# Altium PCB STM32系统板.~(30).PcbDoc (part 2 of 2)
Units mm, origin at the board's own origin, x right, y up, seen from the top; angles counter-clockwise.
Board outline 191.7 x 146.7 mm, 4 copper layers (TopLayer, MidLayer1, MidLayer2, BottomLayer); 154 components, 101 nets, 554 pads, 177 vias.
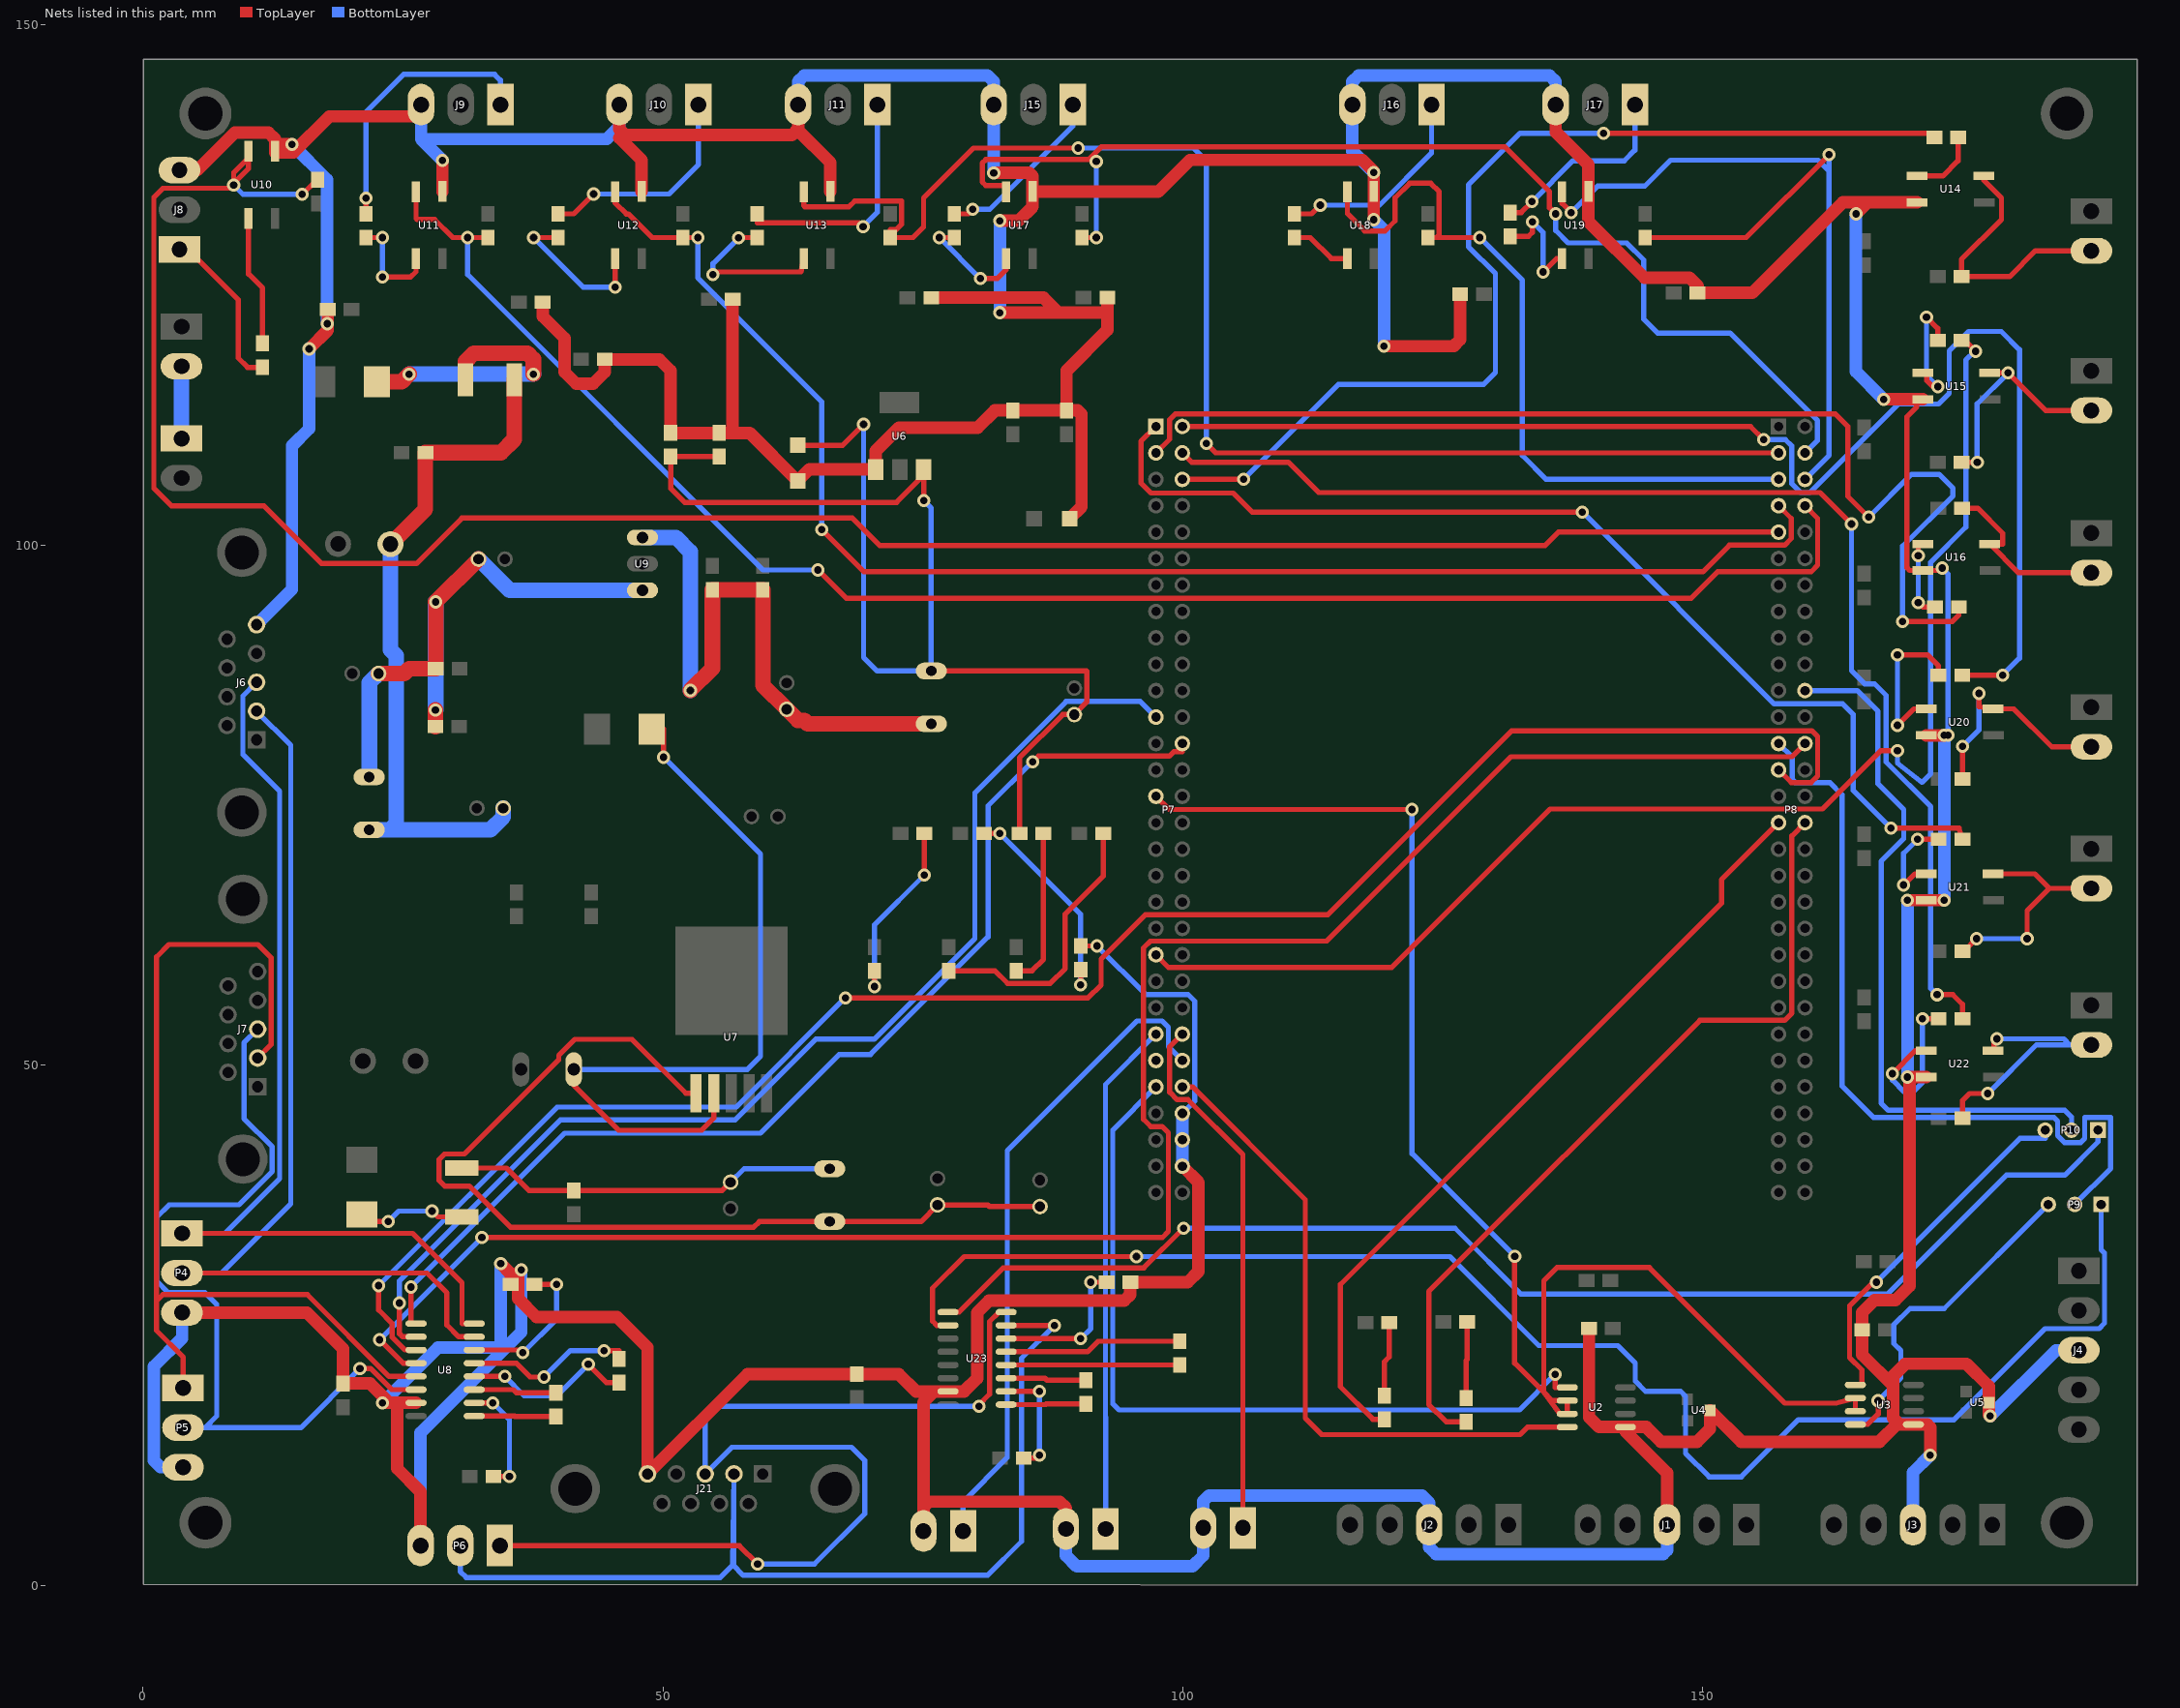
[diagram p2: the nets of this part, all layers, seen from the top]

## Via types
v1: diameter 1.27, hole 0.711, TopLayer to BottomLayer, 177 vias

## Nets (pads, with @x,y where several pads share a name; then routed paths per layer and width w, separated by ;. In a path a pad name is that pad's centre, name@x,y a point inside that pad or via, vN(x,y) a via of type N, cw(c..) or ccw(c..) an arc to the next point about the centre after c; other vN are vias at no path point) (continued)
GND-SYS: C19.1 C20.1 C23.2 C24.2 C25.2 C26.2 C29.2 C30.2 C31.2 C46.2 C48.1 C50.2 C51.1 C54.2 C55.1 C56.1 C57.1 C58.1 C59.1 J1.3 J2.3 J3.3 J4.3 J6.5 J8.3 J9.3 J10.3 J11.3 J15.3 J16.3 J17.3 J21.5 LED6.2 P4.3 P5.3 P6.3 P7.54 P7.56 P7.58 R11.2 S2.2 S3.2 S4.2 U2.5 U3.5 U4.3 U5.3 U6.1 U8.15 U10.3 U11.3 U12.3 U13.3 U14.2 U15.2 U16.2 U17.3 U18.3 U19.3 U20.2 U21.2 U22.2 U23.15 | length 1068.5
  TopLayer w0.5: LED6.2@90.176,61.457 v1(91.725,61.457) ; U15.2@171.15,114.01 170.56,114.01 170.56,113.279 169.62,112.339 169.62,97.821 169.881,97.56 U16.2@171.15,97.56 172.773,97.56 v1(172.998,97.785) ; U20.2@171.474,81.71 v1(173.202,81.71) v1(173.583,81.71)
  TopLayer w1.2: J8.3@3.5,136.05 5.217,136.05 8.837,139.67 12.064,139.67 12.69,139.044 U10.3@12.69,138.527 ; P4.3@3.75,26.2 15.76,26.2 19.232,22.728 C46.2@19.232,19.388 21.834,19.388 23.697,17.525 ; v1(14.325,138.527) U10.3@12.69,138.527 ; v1(15.976,118.867) 17.764,120.656 v1@17.764,121.341 ; v1(17.703,121.28) v1@17.764,121.341 ; C56.1@17.764,122.65 v1@17.764,121.341 ; v1(23.037,17.525) 23.697,17.525 ; U8.15@26.256,17.525 24.434,17.525 ; P6.3@26.69,3.8 26.69,8.961 24.434,11.218 24.434,17.525 ; J9.3@26.74,142.35 26.74,141.219 17.922,141.219 14.469,137.766 12.69,137.766 U10.3@12.69,137.872 U10.3@12.69,138.527 ; U11.3@28.79,134 v1(28.79,136.98) ; v1(34.391,30.907) 35.35,29.948 C31.2@35.35,28.9 ; v1(36.372,30.323) 36.074,30.025 36.074,27.555 37.847,25.782 45.586,25.782 48.515,22.853 J21.5@48.515,10.69 58.113,20.288 C50.2@68.632,20.288 72.668,20.288 74.331,18.625 76.072,18.625 ; C57.1@38.436,123.35 38.436,121.991 40.537,119.89 40.537,116.632 41.655,115.514 43.282,115.514 44.4,116.632 R11.2@44.4,117.85 49.656,117.85 50.732,116.774 C23.2@50.732,110.788 C24.2@55.4,110.788 56.442,110.788 ; J10.3@45.79,142.35 45.79,140 46.209,139.581 ; U12.3@47.95,134 47.95,137.003 45.79,139.163 46.209,139.581 ; C58.1@56.698,123.632 56.698,111.044 56.442,110.788 ; J11.3@62.99,142.35 62.99,140 ; U13.3@66.09,134 66.09,136.774 62.99,139.874 62.99,140 ; U6.1@70.467,107.26 U6.1@70.467,107.285 ; S2.2@75.05,5.2 75.05,7.508 ; C59.1@75.798,123.782 86.6,123.782 88.035,122.347 ; v1(81.8,135.784) 85.216,135.784 85.54,135.46 U17.3@85.54,134 U17.3@85.54,133.98 ; v1(82.397,122.347) 88.035,122.347 ; v1(82.397,131.186) 84.2,131.186 85.54,132.526 U17.3@85.54,133.98 ; S3.2@88.75,5.4 88.75,7.412 88.14,8.022 75.564,8.022 75.05,7.508 ; C30.2@89.114,102.55 90.245,103.681 90.245,112.568 89.875,112.938 C26.2@88.8,112.938 ; C48.1@92.736,123.8 92.736,122.728 ; P7.58@99.94,40.28 101.497,38.723 101.497,30.159 100.456,29.118 C54.2@94.938,29.118 94.938,27.929 94.36,27.351 81.355,27.351 80.212,26.208 80.212,19.883 78.954,18.625 U23.15@77.406,18.625 76.072,18.625 ; v1(118.35,131.288) U18.3@118.35,134 v1(118.35,135.809) 118.35,135.936 117.258,137.028 100.685,137.028 97.637,133.98 U17.3@85.54,133.98 ; v1(119.328,119.121) 126.034,119.121 126.652,119.739 C51.1@126.652,124.118 ; J17.3@135.84,142.35 135.84,139.721 138.99,136.571 U19.3@138.99,134 138.99,131.085 144.375,125.7 148.716,125.7 149.486,124.93 C55.1@149.486,124.25 154.759,124.25 163.459,132.95 165.821,132.95 ; C19.1@139.052,24.668 139.052,16.147 140.004,15.195 U2.5@142.544,15.195 ; J1.3@146.55,5.8 146.55,10.79 142.544,14.796 U2.5@142.544,15.195 ; v1(164.718,131.847) 165.821,132.95 ; v1(167.391,114.01) U15.2@171.15,114.01 ; v1(169.671,65.85) U21.2@171.474,65.85 v1(173.202,65.85) ; U14.2@170.6,132.95 165.821,132.95 ; U22.2@171.474,48.85 v1(169.671,48.85) 169.874,48.647 169.874,28.748 168.528,27.402 166.496,27.402 165.314,26.22 C20.1@165.314,24.55 165.314,22.144 168.299,19.159 ; U20.2@171.474,81.71 v1(173.202,81.71) ; v1(171.855,12.496) 171.855,15.166 171.576,15.445 U3.5@170.244,15.445 168.902,15.445 168.766,15.581 ; v1(177.621,16.251) 177.5,16.372 U5.3@177.5,17.55 177.5,19.116 175.335,21.28 169.468,21.28 168.299,20.112 168.299,19.159 ; 23.697,17.525 24.434,17.525 ; 46.209,139.581 46.374,139.416 62.406,139.416 62.99,140 ; 56.442,110.788 58.333,110.788 C29.2@62.95,106.171 64.064,107.285 U6.1@70.467,107.285 ; U6.1@70.467,107.285 70.467,109.063 72.702,111.298 80.274,111.298 81.914,112.938 C25.2@83.65,112.938 C26.2@88.8,112.938 ; 75.05,7.508 75.05,17.603 76.072,18.625 ; 88.035,122.347 92.355,122.347 92.736,122.728 ; C26.2@88.8,112.938 88.8,116.759 92.736,120.695 92.736,122.728 ; U2.5@142.544,15.195 144.55,15.195 145.958,13.787 149.435,13.787 150.68,15.032 U4.3@150.68,16.8 153.693,13.787 166.972,13.787 168.766,15.581 ; 168.299,19.159 168.299,16.048 168.766,15.581
  BottomLayer w0.5: v1(91.725,61.457) 96.392,56.79 100.481,56.79 101.14,56.131 101.14,46.56 P7.54@99.94,45.36 ; v1(172.998,97.785) 173.583,97.201 v1(173.583,81.71)
  BottomLayer w1.2: P4.3@3.75,26.2 3.758,26.2 3.758,23.744 1.04,21.026 1.04,11.984 1.694,11.33 P5.3@3.85,11.33 ; J6.5@10.92,92.345 14.325,95.75 14.325,109.545 15.976,111.196 v1(15.976,118.867) ; v1(14.325,138.527) 17.703,135.149 v1(17.703,121.28) ; v1(23.037,17.525) 28.342,22.83 34.391,22.83 v1(34.391,30.907) ; P6.3@26.69,3.8 26.69,14.647 36.372,24.328 v1(36.372,30.323) ; J9.3@26.74,142.35 26.74,139.035 ; v1(28.79,136.98) 26.74,139.03 26.74,139.035 ; J10.3@45.79,142.35 45.79,140.249 44.576,139.035 26.74,139.035 ; J11.3@62.99,142.35 62.99,144.572 63.574,145.156 81.216,145.156 81.8,144.572 J15.3@81.8,142.35 v1(81.8,135.784) ; v1(82.397,122.347) v1(82.397,131.186) ; S3.2@88.75,5.4 88.75,2.84 89.791,1.799 100.909,1.799 101.95,2.84 S4.2@101.95,5.5 101.95,8.068 102.488,8.606 122.994,8.606 123.68,7.92 J2.3@123.68,5.8 123.68,3.644 124.332,2.992 146.194,2.992 146.55,3.348 J1.3@146.55,5.8 ; P7.58@99.94,40.28 P7.56@99.94,42.82 P7.54@99.94,45.36 ; v1(118.35,131.288) 119.328,130.31 v1(119.328,119.121) ; v1(118.35,135.809) 116.29,137.869 J16.3@116.29,142.35 116.29,144.572 116.874,145.156 135.256,145.156 135.84,144.572 J17.3@135.84,142.35 ; v1(164.718,131.847) 164.718,116.683 v1(167.391,114.01) ; v1(169.671,48.85) v1(169.671,65.85) ; J3.3@170.2,5.8 170.2,10.841 v1(171.855,12.496) ; v1(173.202,65.85) v1(173.202,81.71) ; v1(177.621,16.251) 183.96,22.59 J4.3@186.15,22.59
IN1: J8.1 R16.2 | length 16
  TopLayer w0.5: J8.1@3.5,128.43 4.317,128.43 9.143,123.604 9.143,118.004 10.057,117.089 11.5,117.089 R16.2@11.5,117.1
IN1_1: P8.9 R22.1 U10.4 | length 214.9
  TopLayer w0.5: v1(8.711,134.615) v1@8.711,134.768 ; U10.4@10.15,137.846 U10.4@10.15,137.257 ; v1(15.315,133.726) 16.611,135.022 16.8,135.022 R22.1@16.8,135.136 ; P8.9@157.276,101.24 136.092,101.24 134.802,99.95 70.857,99.95 68.216,102.591 30.662,102.591 26.288,98.217 17.169,98.217 11.607,103.78 2.717,103.78 1.04,105.456 1.04,133.447 1.904,134.31 8.254,134.31 v1@8.711,134.768 ; v1@8.711,134.768 8.711,135.818 U10.4@10.15,137.257 ; v1@8.711,134.768 10.15,136.206 U10.4@10.15,137.257
  BottomLayer w0.5: v1(8.711,134.615) 9.6,133.726 v1(15.315,133.726)
IN2: J9.1 R17.2 | length 26.8
  TopLayer w0.5: R17.2@21.45,131.85 v1(21.45,133.359)
  BottomLayer w0.5: v1(21.45,133.359) 21.45,141.664 25.043,145.258 33.801,145.258 34.36,144.699 J9.1@34.36,142.35
IN2_2: P8.8 R23.1 U11.4 | length 164
  TopLayer w0.5: U11.4@26.25,133.975 26.25,131.41 26.365,131.295 28.048,131.295 29.779,129.564 v1(31.216,129.564) R23.1@33.15,129.564 ; v1(64.896,97.607) 67.614,94.89 148.868,94.89 151.408,97.43 160.4,97.43 161.035,98.065 161.035,102.561 P8.8@159.816,103.78
  BottomLayer w0.5: v1(31.216,129.564) 31.216,126.005 59.613,97.607 v1(64.896,97.607)
IN3: J10.1 R18.2 | length 21.2
  TopLayer w0.5: R18.2@39.907,131.85 41.426,131.85 v1(43.328,133.752)
  BottomLayer w0.5: v1(43.328,133.752) 50.57,133.752 53.41,136.591 J10.1@53.41,142.35
IN3_3: P8.7 R24.1 U12.4 | length 143.3
  TopLayer w0.5: U12.4@45.41,133.975 45.41,132.888 46.473,131.825 46.678,131.825 48.939,129.564 R24.1@51.9,129.564 v1(53.339,129.564) ; v1(65.252,101.494) 69.316,97.43 149.986,97.43 152.551,99.995 157.86,99.995 158.495,100.63 158.495,102.561 P8.7@157.276,103.78
  BottomLayer w0.5: v1(53.339,129.564) 53.339,125.7 65.252,113.787 v1(65.252,101.494)
IN4: J17.1 R32.2 | length 18.9
  TopLayer w0.5: R32.2@131.45,131.968 132.519,131.968 v1(133.567,133.016)
  BottomLayer w0.5: v1(133.567,133.016) 137.503,136.952 142.444,136.952 143.46,137.968 J17.1@143.46,142.35
IN4_4: P8.6 R38.1 U19.4 | length 82.8
  TopLayer w0.5: U19.4@136.45,133.975 136.45,132.86 v1(137.337,131.974) ; R38.1@144.45,129.564 154.155,129.564 v1(162.127,137.536)
  BottomLayer w0.5: v1(137.337,131.974) 139.877,134.514 144.398,134.514 146.887,137.003 161.06,137.003 162.127,135.936 ; P8.6@159.816,106.32 162.127,108.631 162.127,135.936 ; v1(162.127,137.536) 162.127,135.936
IN5: J16.1 R31.2 | length 20.3
  TopLayer w0.5: R31.2@110.707,131.85 112.372,131.85 v1(113.207,132.685)
  BottomLayer w0.5: v1(113.207,132.685) 118.906,132.685 123.91,137.689 J16.1@123.91,142.35
IN5_5: P8.5 R37.1 U18.4 | length 72.9
  TopLayer w0.5: U18.4@115.81,133.975 115.81,131.872 117.479,130.203 119.43,130.203 120.395,131.168 120.395,133.396 121.792,134.793 123.824,134.793 124.637,133.98 124.637,129.84 124.361,129.564 ; R37.1@123.55,129.564 124.361,129.564 ; v1(128.548,129.564) 124.361,129.564
  BottomLayer w0.5: v1(128.548,129.564) 132.638,125.475 132.638,108.606 134.923,106.32 P8.5@157.276,106.32
IN6: J15.1 R30.2 | length 17
  TopLayer w0.5: R30.2@78.007,131.85 79.352,131.85 v1(79.78,132.278)
  BottomLayer w0.5: v1(79.78,132.278) 81.406,132.278 89.42,140.292 J15.1@89.42,142.35
IN6_6: P8.4 R36.1 U17.4 | length 114.9
  TopLayer w0.5: U17.4@83,133.975 83,134.564 81.05,134.564 80.695,134.92 80.695,136.723 81.044,137.072 90.932,137.072 ; R36.1@90.3,129.564 v1(91.668,129.564) ; v1(91.668,136.876) 90.932,137.072 ; v1(135.838,131.847) 135.251,132.434 135.251,133.983 130.961,138.273 92.132,138.273 90.932,137.072
  BottomLayer w0.5: v1(91.668,129.564) v1(91.668,136.876) ; v1(135.838,131.847) 135.838,130.246 137.032,129.053 142.671,129.053 144.322,127.402 144.322,121.712 145.643,120.391 152.602,120.391 161.016,111.977 161.016,110.06 P8.4@159.816,108.86
IN7: J11.1 R19.2 | length 23.5
  TopLayer w0.5: R19.2@59.057,131.85 59.057,131.001 68.866,131.001 v1(69.239,130.627)
  BottomLayer w0.5: v1(69.239,130.627) 70.61,131.998 J11.1@70.61,142.35
IN7_7: P8.3 R25.1 U13.4 | length 134
  TopLayer w0.5: U13.4@63.55,133.975 63.55,132.637 63.652,132.535 67.896,132.535 68.427,133.066 72.948,133.066 72.948,130.856 72.44,130.348 71.85,130.348 R25.1@71.85,129.564 74.04,129.564 75.056,130.58 75.056,133.371 79.857,138.171 v1(89.915,138.171) ; v1(102.234,109.774) 103.148,108.86 156.209,108.86 P8.3@157.276,108.86
  BottomLayer w0.5: v1(89.915,138.171) 101.015,138.171 102.234,136.952 v1(102.234,109.774)
KEY1: P7.48 S4.1 | length 51.5
  TopLayer w0.5: P7.48@99.94,52.98 98.729,51.769 98.729,47.392 99.44,46.68 100.481,46.68 105.76,41.402 S4.1@105.76,5.5
KEY2: P7.47 S3.1 | length 49.6
  BottomLayer w0.5: S3.1@92.56,5.4 92.56,16.132 92.55,16.143 92.55,48.13 P7.47@97.4,52.98
KEY3: P7.50 S2.1 | length 63
  BottomLayer w0.5: S2.1@78.86,5.2 78.86,8.022 83.108,12.269 83.108,41.778 95.579,54.25 97.992,54.25 98.602,53.64 98.602,51.778 P7.50@99.94,50.44
KEY4: P7.49
L1: P7.2 R33.2 | length 130.6
  TopLayer w0.5: P7.2@99.94,111.4 154.583,111.4 v1(155.853,110.13) ; R33.2@174.936,87.5 v1(178.815,87.5)
  BottomLayer w0.5: v1(155.853,110.13) 157.936,110.13 158.546,109.52 158.546,105.888 159.384,105.05 160.273,105.05 168.782,113.559 172.643,113.559 173.684,114.6 173.684,118.664 175.564,120.544 178.688,120.544 180.441,118.791 180.441,89.126 v1(178.815,87.5)
L1_OUT: J18.2 R39.2 U20.4 | length 22.5
  TopLayer w0.5: R39.2@174.95,77.5 v1(174.95,80.64) ; v1(176.554,85.746) 176.554,84.445 U20.4@177.9,84.25 179.892,84.25 183.542,80.6 J18.2@187.35,80.6
  BottomLayer w0.5: v1(174.95,80.64) 176.554,82.245 v1(176.554,85.746)
L2: P7.1 R34.2 | length 103.9
  TopLayer w0.5: P7.1@97.4,111.4 95.96,109.96 95.96,105.964 96.925,104.999 104.825,104.999 106.654,103.17 v1(138.404,103.17) ; v1(168.071,72.792) 174.624,72.792 R34.2@174.95,71.7
  BottomLayer w0.5: v1(138.404,103.17) 156.844,84.73 163.448,84.73 164.464,83.714 164.464,76.398 v1(168.071,72.792)
L2_out: J19.2 R40.2 U21.4 | length 22.5
  TopLayer w0.5: R40.2@174.95,60.95 175.101,60.95 v1(176.3,62.149) ; U21.4@177.9,68.39 181.914,68.39 183.314,66.99 ; v1(181.177,62.149) 181.177,64.856 183.311,66.99 183.314,66.99 ; J19.2@187.35,66.99 183.314,66.99
  BottomLayer w0.5: v1(176.3,62.149) v1(181.177,62.149)
L3: P7.4 R35.2 | length 120.6
  TopLayer w0.5: P7.4@99.94,108.86 100.829,107.971 110.133,107.971 113.054,105.05 161.264,105.05 v1(164.286,102.027) ; v1(172.516,56.764) 174.036,56.764 174.95,55.85 R35.2@174.95,54.443
  BottomLayer w0.5: v1(164.286,102.027) 164.286,87.93 165.556,86.66 166.496,86.66 167.614,85.542 167.614,79.142 171.906,74.849 171.906,57.374 v1(172.516,56.764)
L3_out: J20.2 R41.2 U22.4 | length 24.9
  TopLayer w0.5: R41.2@174.95,44.9 174.95,46.579 175.636,47.265 v1(177.393,47.265) ; U22.4@177.9,51.39 177.977,51.39 177.977,52.243 v1(178.256,52.522)
  BottomLayer w0.5: v1(177.393,47.265) 182.068,51.94 185.292,51.94 ; v1(178.256,52.522) 184.71,52.522 185.292,51.94 ; J20.2@187.35,51.94 185.292,51.94
L4: P7.3 R28.2 | length 110.8
  TopLayer w0.5: P7.3@97.4,108.86 98.729,110.189 98.729,112.06 99.288,112.619 162.711,112.619 163.928,111.402 163.928,104.697 v1(165.937,102.687) ; v1(169.207,92.654) 174.003,92.654 174.613,93.264 R28.2@174.613,94.043
  BottomLayer w0.5: v1(165.937,102.687) 170.052,106.802 172.708,106.802 174.04,105.47 174.04,104.74 169.207,99.907 v1(169.207,92.654)
L4_out: J14.2 R29.2 U16.4 | length 18.1
  TopLayer w0.5: R29.2@174.913,103.543 176.427,103.543 178.826,101.144 178.826,100.1 U16.4@177.576,100.1 180.336,97.34 J14.2@187.35,97.34
L5: P7.6 R20.2 | length 100.7
  TopLayer w0.5: P7.6@99.94,106.32 v1(105.816,106.32) ; v1(140.436,139.594) 172.25,139.594 R20.2@172.25,139.2
  BottomLayer w0.5: v1(105.816,106.32) 114.934,115.438 128.904,115.438 130.047,116.581 130.047,126.106 127.456,128.697 127.456,134.615 132.435,139.594 v1(140.436,139.594)
L5_out: J12.2 R26.2 U14.4 | length 25.5
  TopLayer w0.5: U14.4@177.026,135.49 177.026,135.058 178.713,133.371 178.713,131.303 174.863,127.452 R26.2@174.863,125.807 179.481,125.807 181.964,128.29 J12.2@187.35,128.29
L6: P7.41 R21.2 | length 130.1
  TopLayer w0.5: P7.41@97.4,60.6 98.62,59.38 120.065,59.38 135.305,74.62 161.492,74.62 167.106,80.234 v1(168.706,80.234) ; R21.2@174.863,119.693 175.17,119.693 v1(176.224,118.639)
  BottomLayer w0.5: v1(168.706,80.234) 168.706,79.04 171.068,77.186 171.906,78.024 171.906,98.344 175.284,101.722 175.284,117.775 176.148,118.639 v1(176.224,118.639)
L6_out: J13.2 R27.2 U15.4 | length 22.6
  TopLayer w0.5: R27.2@174.863,107.943 v1(176.377,107.943) ; U15.4@177.576,116.55 v1@179.343,116.55 ; v1(179.348,116.556) v1@179.343,116.55 ; J13.2@187.35,112.94 182.948,112.94 v1@179.343,116.55
  BottomLayer w0.5: v1(176.377,107.943) 176.377,113.584 v1(179.348,116.556)
LED1: LED1.2 P8.32 | length 80
  TopLayer w0.5: LED1.2@127.224,15.709 125.306,15.709 123.646,17.369 123.646,28.24 149.707,54.3 157.86,54.3 158.546,54.986 158.546,72.03 P8.32@159.816,73.3
LED2: LED2.2 P8.31 | length 77.2
  TopLayer w0.5: LED2.2@119.374,15.943 118.265,15.943 115.137,19.071 115.137,28.9 151.789,65.553 151.789,67.813 P8.31@157.276,73.3
NetC21_1: C21.1 C27.1 F1.2 L4.1 | length 37.1
  TopLayer w0.5: F1.2@30.65,40.1 34.949,40.1 37.101,37.948 C27.1@41.418,37.948 55.707,37.948 C21.1@56.5,38.741
  BottomLayer w0.5: C21.1@56.5,38.741 57.794,40.035 L4.1@66.033,40.035
NetC22_1: C22.1 C28.1 L4.2 U7.1 | length 94.5
  TopLayer w0.5: U7.1@53.175,47.29 52.196,47.29 47.014,52.472 41.528,52.472 39.979,50.922 39.979,50.516 30.911,41.448 28.98,41.448 28.472,40.94 28.472,38.908 29.006,38.375 31.368,38.375 35.356,34.387 58.698,34.387 59.266,34.955 L4.2@66.033,34.955 74.804,34.955 C22.1@76.4,36.551 81.228,36.551 81.378,36.401 C28.1@86.25,36.401
NetC31_1: C31.1 U8.6 | length 14.8
  TopLayer w0.5: U8.6@31.844,22.605 36.27,22.605 v1(36.523,22.352) ; C31.1@37.636,28.9 v1(39.775,28.9)
  BottomLayer w0.5: v1(36.523,22.352) 39.775,25.604 v1(39.775,28.9)
NetC32_1: C32.1 C33.1 C42.1 F2.2 L5.1 | length 67.2
  TopLayer w1.5: C32.1@23.794,100.091 27.148,103.445 C42.1@27.148,108.882 34.416,108.882 35.699,110.165 F2.2@35.699,115.9
  BottomLayer w1.5: L5.1@21.75,72.62 23.748,72.62 ; C32.1@23.794,100.091 23.794,89.916 24.358,89.352 24.358,73.23 23.748,72.62 ; C33.1@34.64,74.7 34.64,73.86 33.4,72.62 23.748,72.62
NetC34_1: C34.1 C35.1 C36.1 C43.1 L5.2 U9.1 | length 57.3
  TopLayer w1.5: C34.1@22.65,87.65 25.119,87.65 25.587,88.118 C35.1@28.152,88.118 v1@28.152,94.524 ; C36.1@28.114,82.55 v1(28.114,84.145) ; v1(28.142,94.534) v1@28.152,94.524 ; C43.1@32.26,98.65 28.152,94.542 v1@28.152,94.524
  BottomLayer w1.5: L5.2@21.75,77.7 21.767,77.7 21.767,86.767 C34.1@22.65,87.65 ; v1(28.114,84.145) 28.142,84.174 v1(28.142,94.534) ; C43.1@32.26,98.65 35.26,95.65 U9.1@48.025,95.65
NetC37_1: C37.1 C38.1 C39.1 L6.1 U9.3 | length 60.8
  TopLayer w1.5: v1(52.628,86.025) 54.75,88.147 C37.1@54.75,95.702 C38.1@59.6,95.702 59.6,86.51 C39.1@61.9,84.21 62.966,83.144 63.593,83.144 63.917,82.82 L6.1@75.8,82.82
  BottomLayer w1.5: U9.3@48.021,100.735 51.253,100.735 52.628,99.36 v1(52.628,86.025)
NetC40_1: C40.1 U8.1 | length 7.9
  TopLayer w0.5: U8.1@31.844,16.255 35.737,16.255 35.778,16.214 C40.1@39.7,16.214
NetC40_2: C40.2 U8.3 | length 8
  TopLayer w0.5: U8.3@31.844,18.795 35.61,18.795 35.905,18.5 C40.2@39.7,18.5
NetC41_1: C41.1 U8.5 | length 16.3
  TopLayer w0.5: U8.5@31.844,21.335 35.895,21.335 37.219,20.01 v1(38.556,20.01) ; v1(44.322,22.55) 45.768,22.55 C41.1@45.768,21.748
  BottomLayer w0.5: v1(38.556,20.01) 41.096,22.55 v1(44.322,22.55)
NetC41_2: C41.2 U8.4 | length 16.7
  TopLayer w0.5: U8.4@31.844,20.065 v1(34.797,20.065) ; v1(42.816,21.222) 44.576,19.462 C41.2@45.768,19.462
  BottomLayer w0.5: v1(34.797,20.065) 36.655,18.207 39.801,18.207 v1(42.816,21.222)
NetC45_2: C45.2 U8.2 | length 11
  TopLayer w0.5: U8.2@31.844,17.525 v1(33.629,17.525) ; C45.2@33.7,10.45 35.219,10.45 v1(35.229,10.46)
  BottomLayer w0.5: v1(33.629,17.525) 35.229,15.925 v1(35.229,10.46)
NetC49_2: C49.2 U23.2 | length 11
  TopLayer w0.5: U23.2@82.994,18.625 v1(86.207,18.625) ; C49.2@84.688,12.218 85.933,12.218 v1(86.207,12.492)
  BottomLayer w0.5: v1(86.207,12.492) v1(86.207,18.625)
NetC52_1: C52.1 U23.1 | length 7.7
  TopLayer w0.5: U23.1@82.994,17.355 86.791,17.355 86.845,17.409 C52.1@90.65,17.409
NetC52_2: C52.2 U23.3 | length 7.7
  TopLayer w0.5: U23.3@82.994,19.895 86.715,19.895 86.915,19.695 C52.2@90.65,19.695
NetC53_1: C53.1 U23.5 | length 17.1
  TopLayer w0.5: U23.5@82.994,22.435 90.829,22.435 91.844,23.45 C53.1@99.7,23.45
NetC53_2: C53.2 U23.4 | length 16.7
  TopLayer w0.5: U23.4@82.994,21.165 91.337,21.165 91.338,21.164 C53.2@99.7,21.164
NetC54_1: C54.1 U23.6 | length 14.5
  TopLayer w0.5: U23.6@82.994,23.705 v1(90.169,23.705) ; v1(91.134,29.129) 91.145,29.118 C54.1@92.652,29.118
  BottomLayer w0.5: v1(90.169,23.705) 91.134,24.67 v1(91.134,29.129)
NetD1_2: D1.2 L3.2 U7.2 | length 74.6
  TopLayer w0.5: L3.2@41.413,49.579 41.413,48.052 45.731,43.734 53.72,43.734 54.875,44.889 U7.2@54.875,47.29 ; D1.2@48.917,82.31 50.062,82.31 v1(50.062,79.599)
  BottomLayer w0.5: L3.2@41.413,49.579 41.413,49.576 58.114,49.576 59.384,50.846 59.384,70.277 v1(50.062,79.599)
NetD2_2: D2.2 F1.1 | length 10.9
  TopLayer w0.5: D2.2@21.05,35.64 21.05,34.946 v1(23.57,34.946) ; v1(27.787,35.962) 28.347,35.401 F1.1@30.65,35.401
  BottomLayer w0.5: v1(23.57,34.946) 24.586,35.962 v1(27.787,35.962)
NetD3_2: D3.2 F2.1 | length 25.7
  TopLayer w1.5: D3.2@22.5,115.7 24.866,115.7 v1(25.594,116.429) ; F2.1@31,115.9 31,117.648 31.813,118.461 36.956,118.461 37.54,117.877 v1(37.54,116.429)
  BottomLayer w1.5: v1(25.594,116.429) v1(37.54,116.429)
NetLED1_1: LED1.1 R4.1 | length 7.4
  TopLayer w0.5: LED1.1@127.224,17.995 127.224,21.585 127.323,21.684 R4.1@127.323,25.307
NetLED2_1: LED2.1 R5.1 | length 7.2
  TopLayer w0.5: LED2.1@119.374,18.229 119.374,21.484 119.836,21.946 R5.1@119.836,25.25
NetLED3_1: LED3.1 R15.1 | length 18.2
  TopLayer w0.5: LED3.1@70.326,59.071 70.326,57.557 v1(70.332,57.552) ; v1(75.125,68.27) R15.1@75.125,72.259
  BottomLayer w0.5: v1(70.332,57.552) 70.332,63.477 v1(75.125,68.27)
NetLED4_1: LED4.1 R12.1 | length 26.8
  TopLayer w0.5: LED4.1@77.476,59.071 81.914,59.071 83.129,57.856 87.248,57.856 88.67,59.279 88.67,64.511 92.325,68.166 R12.1@92.325,72.259
NetLED5_1: LED5.1 R13.1 | length 15.2
  TopLayer w0.5: LED5.1@83.976,59.071 85.491,59.071 86.575,60.155 R13.1@86.575,72.259
NetLED6_1: LED6.1 R14.1 | length 20.8
  TopLayer w0.5: R14.1@80.875,72.259 v1(82.397,72.259) ; v1(90.169,57.695) 90.176,57.702 LED6.1@90.176,59.171
  BottomLayer w0.5: v1(82.397,72.259) 90.169,64.486 v1(90.169,57.695)
NetP2_1: P2.1 S1.2 | length 7
  BottomLayer w1.5: P2.1@3.7,110.25 3.707,110.25 3.707,117.19 S1.2@3.7,117.19
NetR16_1: R16.1 U10.1 | length 12.6
  TopLayer w0.5: U10.1@10.15,131.42 10.15,126.059 11.5,124.709 R16.1@11.5,119.386
NetR17_1: R17.1 U11.1 | length 10.1
  TopLayer w0.5: R17.1@21.45,129.564 v1(23.037,129.564) ; v1(23.037,125.776) 25.742,125.776 26.25,126.284 U11.1@26.25,127.548
  BottomLayer w0.5: v1(23.037,125.776) v1(23.037,129.564)
NetR18_1: R18.1 U12.1 | length 14.9
  TopLayer w0.5: v1(37.566,129.564) R18.1@39.907,129.564 ; v1(45.41,124.789) U12.1@45.41,127.548
  BottomLayer w0.5: v1(37.566,129.564) 42.341,124.789 v1(45.41,124.789)
NetR19_1: R19.1 U13.1 | length 16.2
  TopLayer w0.5: v1(54.812,126.005) 55.066,126.259 63.271,126.259 U13.1@63.55,127.548 ; v1(57.276,129.535) 57.305,129.564 R19.1@59.057,129.564
  BottomLayer w0.5: v1(54.812,126.005) 54.812,127.071 v1(57.276,129.535)
NetR20_1: R20.1 U14.1 | length 6.8
  TopLayer w0.5: U14.1@170.6,135.49 173.074,135.49 174.536,136.952 R20.1@174.536,139.2
NetR21_1: R21.1 U15.1 | length 12.2
  TopLayer w0.5: U15.1@171.15,116.55 171.525,116.55 171.525,115.794 172.084,115.235 v1(172.592,115.235) ; v1(171.5,121.915) 172.577,120.838 R21.1@172.577,119.693
  BottomLayer w0.5: v1(171.5,121.915) 171.5,116.327 v1(172.592,115.235)
NetR28_1: R28.1 U16.1 | length 7.9
  TopLayer w0.5: v1(170.712,94.458) 171.127,94.043 R28.1@172.327,94.043 ; v1(170.712,98.979) 170.712,100.1 U16.1@171.15,100.1
  BottomLayer w0.5: v1(170.712,94.458) v1(170.712,98.979)
NetR30_1: R30.1 U17.1 | length 10.9
  TopLayer w0.5: v1(76.58,129.564) R30.1@78.007,129.564 ; v1(80.52,125.624) 82.143,125.624 83,126.481 U17.1@83,127.548
  BottomLayer w0.5: v1(76.58,129.564) v1(80.52,125.624)
NetR31_1: R31.1 U18.1 | length 5.9
  TopLayer w0.5: R31.1@110.707,129.564 112.242,129.564 114.257,127.548 U18.1@115.81,127.548
NetR32_1: R32.1 U19.1 | length 10.9
  TopLayer w0.5: R32.1@131.45,129.682 133.221,129.682 133.604,130.064 v1(133.603,131.085) ; v1(134.644,126.259) 135.934,127.548 U19.1@136.45,127.548
  BottomLayer w0.5: v1(133.603,131.085) 134.644,130.043 v1(134.644,126.259)
NetR33_1: R33.1 U20.1 | length 15.5
  TopLayer w0.5: v1(168.706,82.672) 170.284,84.25 U20.1@171.474,84.25 ; v1(168.706,89.454) 171.576,89.454 172.65,88.38 R33.1@172.65,87.5
  BottomLayer w0.5: v1(168.706,82.672) v1(168.706,89.454)
NetR34_1: R34.1 U21.1 | length 9.6
  TopLayer w0.5: v1(169.301,67.315) 170.376,68.39 U21.1@171.474,68.39 ; v1(170.636,71.699) R34.1@172.664,71.7
  BottomLayer w0.5: v1(169.301,67.315) 169.301,70.365 v1(170.636,71.699)
NetR35_1: R35.1 U22.1 | length 16.2
  TopLayer w0.5: v1(168.223,49.18) 170.433,51.39 U22.1@171.474,51.39 ; v1(171.119,54.443) R35.1@172.664,54.443
  BottomLayer w0.5: v1(168.223,49.18) 168.223,48.56 169.365,47.418 170.18,47.418 171.119,48.357 v1(171.119,54.443)
RS232_RX1: J21.3 P6.1 U23.8 | length 102.6
  TopLayer w0.5: P6.1@34.31,3.8 34.31,3.78 57.352,3.78 v1(59.105,2.027) ; v1(80.39,17.191) 80.39,17.343 81.406,18.359 81.406,25.356 82.295,26.245 U23.8@82.994,26.245
  BottomLayer w0.5: v1(59.105,2.027) 64.566,2.027 69.392,6.853 69.392,11.984 68.122,13.254 56.619,13.254 J21.3@54.055,10.69 54.055,16.048 55.198,17.191 v1(80.39,17.191)
RS232_RX2: J6.3 P4.1 U8.8 | length 95.3
  TopLayer w0.5: P4.1@3.75,33.82 25.92,33.82 30.671,29.069 30.671,25.145 U8.8@31.844,25.145
  BottomLayer w0.5: P4.1@3.75,33.82 7.862,33.82 13.13,39.088 13.13,76.335 9.6,79.865 9.6,85.485 J6.3@10.92,86.805
RS232_RX4: J7.2 P5.1 U8.13 | length 93.2
  TopLayer w0.5: P5.1@3.85,18.95 3.86,18.95 3.86,21.915 1.294,24.481 1.294,27.326 ; J7.2@11.02,50.685 12.318,51.983 12.318,60.32 11.048,61.59 2.488,61.59 1.294,60.396 1.294,27.326 ; U8.13@26.256,20.065 23.668,20.065 15.798,27.935 1.904,27.935 1.294,27.326
RS232_TX1: J21.2 P6.2 U23.7 | length 103.3
  TopLayer w0.5: U23.7@82.994,24.975 v1(87.654,24.975)
  BottomLayer w0.5: P6.2@30.5,3.8 30.5,1.316 31.084,0.732 55.504,0.732 56.711,1.938 ; v1(87.654,24.975) 84.479,21.8 84.479,4.212 81.21,0.942 57.707,0.942 56.711,1.938 ; 56.711,1.938 56.825,2.053 J21.2@56.825,10.69 56.711,1.938
RS232_TX2: J6.2 P4.2 U8.7 | length 94.4
  TopLayer w0.5: P4.2@3.75,30.01 27.304,30.01 29.223,28.091 29.223,25.004 30.352,23.875 U8.7@31.844,23.875
  BottomLayer w0.5: P4.2@3.75,30.01 7.543,30.01 14.204,36.672 14.204,80.751 J6.2@10.92,84.035
RS232_TX4: J7.3 P5.2 U8.14 | length 79.1
  TopLayer w0.5: v1(20.852,20.823) 21.884,20.823 23.912,18.795 U8.14@26.256,18.795
  BottomLayer w0.5: P5.2@3.85,15.14 5.968,15.14 ; J7.3@11.02,53.455 9.702,52.137 9.702,44.86 12.43,42.132 12.43,39.788 9.213,36.571 2.514,36.571 1.294,35.352 1.294,29.256 2.437,28.113 5.968,28.113 7.086,26.995 7.086,16.258 5.968,15.14 ; v1(20.852,20.823) 15.169,15.14 5.968,15.14
U_R\E\2: P7.29 U2.2 U2.3 U3.2 U3.3 | length 141.5
  TopLayer w0.5: P7.29@97.4,75.84 98.67,74.57 v1(122.031,74.57) ; v1(131.901,31.618) 131.901,21.342 134.695,18.548 ; U3.3@164.656,16.715 U3.2@164.656,17.985 162.806,17.496 157.885,17.496 144.855,30.526 135.965,30.526 134.695,29.256 134.695,18.548 ; 134.695,18.548 134.695,18.537 136.245,16.465 U2.3@136.956,16.465 U2.2@136.956,17.735 135.508,17.735 134.695,18.548
  BottomLayer w0.5: v1(122.031,74.57) 122.031,41.488 v1(131.901,31.618)
U_RX2: P7.26 U8.9 | length 107.7
  TopLayer w0.5: v1(25.755,28.658) 25.755,25.145 U8.9@26.256,25.145 ; v1(85.546,79.142) 86.105,79.7 98.678,79.7 99.11,80.132 99.94,80.132 P7.26@99.94,80.92
  BottomLayer w0.5: v1(25.755,28.658) 40.551,43.455 59.379,43.455 66.948,51.024 69.951,51.024 81.254,62.327 81.254,74.925 85.47,79.142 v1(85.546,79.142)
U_RX3: P7.51 U2.1 | length 78.8
  TopLayer w0.5: v1(135.787,20.264) 135.787,19.005 U2.1@136.956,19.005
  BottomLayer w0.5: P7.51@97.4,47.9 93.25,43.75 93.25,17.438 93.852,16.835 132.358,16.835 v1(135.787,20.264)
U_RX4: P8.26 U8.12 | length 185.2
  TopLayer w0.5: v1(22.757,23.592) 25.014,21.335 U8.12@26.256,21.335 ; v1(32.587,33.422) 98.018,33.422 98.602,34.006 98.602,43.48 97.992,44.09 96.9,44.09 96.2,44.79 96.2,61.26 96.86,61.92 113.816,61.92 131.546,79.65 158.546,79.65 P8.26@159.816,80.92
  BottomLayer w0.5: v1(22.757,23.592) v1(32.587,33.422)
U_RX5: P8.22 P10.2 | length 67.6
  BottomLayer w0.5: P8.22@159.816,86 164.85,86 166.826,84.024 166.826,77.059 169.315,74.57 169.315,71.776 167.131,69.591 167.131,46.35 167.831,45.65 184.804,45.65 185.45,45.004 P10.2@185.45,43.75
U_RX5-232: P10.1 U23.9 | length 123.7
  TopLayer w0.5: U23.9@77.406,26.245 78.46,26.245 82.715,30.5 96.239,30.5 v1(100.05,34.311)
  BottomLayer w0.5: v1(100.05,34.311) 126.161,34.311 132.485,27.986 167.757,27.986 179.186,39.415 184.783,39.415 187.99,42.622 P10.1@187.99,43.75
U_RX5-485: P10.3 U3.1 | length 35
  TopLayer w0.5: U3.1@164.656,19.255 165.295,19.255 165.295,20.678 164.102,21.871 164.102,26.863 166.368,29.129 v1(166.673,29.129)
  BottomLayer w0.5: v1(166.673,29.129) 180.516,42.972 182.91,42.972 P10.3@182.91,43.75
U_TX2: P7.23 U8.10 | length 111.4
  TopLayer w0.5: v1(24.662,27.122) v1(24.662,27.122) 24.664,24.175 24.963,23.875 U8.10@26.256,23.875
  BottomLayer w0.5: v1(24.662,27.122) 24.662,29.256 40.131,44.725 56.92,44.725 64.693,52.497 70.306,52.497 79.984,62.174 79.984,76.17 88.772,84.958 95.902,84.958 P7.23@97.4,83.46
U_TX3: P7.52 U2.4 | length 63.5
  TopLayer w0.5: P7.52@99.94,47.9 100.913,47.9 111.759,37.054 111.759,16.048 113.334,14.473 132.424,14.473 133.146,15.195 U2.4@136.956,15.195
U_TX4: P8.27 U8.11 | length 178.8
  TopLayer w0.5: v1(22.652,28.801) 22.652,26.451 23.964,25.139 23.964,23.827 25.186,22.605 U8.11@26.256,22.605 ; v1(67.538,56.459) 90.88,56.459 92.125,57.704 92.125,60.193 96.392,64.46 113.943,64.46 131.622,82.139 160.476,82.139 161.035,81.58 161.035,77.795 160.4,77.16 158.496,77.16 P8.27@157.276,78.38
  BottomLayer w0.5: v1(22.652,28.801) 39.82,45.969 57.047,45.969 v1(67.538,56.459)
U_TX5: P8.25 P9.2 | length 78.3
  BottomLayer w0.5: P8.25@157.276,80.92 158.597,79.599 158.597,77.44 158.876,77.16 162.203,77.16 163.372,75.992 163.372,47.998 166.42,44.95 183.768,44.95 184.11,44.608 184.11,43.214 184.784,42.54 186.308,42.54 186.714,42.947 186.714,44.953 189.204,44.953 189.204,40.054 P9.2@185.75,36.6
U_TX5-232: P9.1 U23.10 | length 149.4
  TopLayer w0.5: U23.10@77.406,24.975 76.326,24.975 75.92,25.381 75.92,28.545 78.968,31.593 v1(95.528,31.593)
  BottomLayer w0.5: v1(95.528,31.593) 125.653,31.593 134.213,23.033 141.808,23.033 143.492,21.349 143.492,19.621 144.481,18.632 147.852,18.632 148.335,18.149 148.335,12.67 150.596,10.409 153.694,10.409 159.181,15.896 174.141,15.896 182.904,24.659 188.086,24.659 188.619,25.192 188.619,31.923 188.29,32.252 P9.1@188.29,36.6
U_TX5-485: P9.3 U3.4 | length 32
  TopLayer w0.5: U3.4@164.656,15.445 165.842,15.445 166.852,16.454 v1(166.852,17.724)
  BottomLayer w0.5: v1(166.852,17.724) 169.036,19.909 169.036,22.55 168.35,23.236 168.35,25.014 169.922,26.586 173.196,26.586 P9.3@183.21,36.6
VCC5V: C23.1 C24.1 C29.1 C44.1 L6.2 R13.2 U6.3 | length 123.9
  TopLayer w0.5: C24.1@55.4,108.502 C23.1@50.732,108.502 50.732,105.456 52.078,104.11 72.465,104.11 U6.3@75.067,106.712 ; C29.1@62.95,109.6 67.287,109.6 v1(69.29,111.603) ; v1(75.067,104.288) U6.3@75.067,106.712 ; U6.3@75.067,107.26 U6.3@75.067,106.712 ; L6.2@75.8,87.9 90.732,87.9 90.753,87.879 90.753,84.903 C44.1@89.55,83.7 88.441,83.7 84.289,79.548 R13.2@84.289,72.259
  BottomLayer w0.5: v1(69.29,111.603) 69.29,89.2 70.59,87.9 L6.2@75.793,87.9 ; v1(75.067,104.288) 75.793,103.562 L6.2@75.793,87.9 ; L6.2@75.8,87.9 L6.2@75.793,87.9
pads on no net: J6.1 J6.4 J6.7 J6.9 J6.10 J6.11 J7.1 J7.4 J7.7 J7.9 J7.10 J7.11 J21.1 J21.4 J21.7 J21.9 J21.10 J21.11 P7.5 P7.7 P7.8 P7.9 P7.10 P7.11 P7.12 P7.13 P7.14 P7.15 P7.16 P7.17 P7.18 P7.19 P7.20 P7.21 P7.22 P7.24 P7.25 P7.27 P7.28 P7.30 P7.31 P7.32 P7.33 P7.34 P7.35 P7.36 P7.37 P7.38 P7.39 P7.40 P7.42 P7.43 P7.44 P7.45 P7.46 P7.59 P7.60 P8.1 P8.2 P8.10 P8.11 P8.12 P8.13 P8.14 P8.15 P8.16 P8.17 P8.18 P8.19 P8.20 P8.21 P8.23 P8.24 P8.28 P8.29 P8.30 P8.33 P8.34 P8.35 P8.36 P8.37 P8.38 P8.39 P8.40 P8.41 P8.42 P8.43 P8.44 P8.45 P8.46 P8.47 P8.48 P8.49 P8.50 P8.51 P8.52 P8.53 P8.54 P8.55 P8.56 P8.57 P8.58 P8.59 P8.60 U23.11 U23.12 U23.13 U23.14

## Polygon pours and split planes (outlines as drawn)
no net on BottomLayer (solid, pour order 0): 0.05,146.7 0.3,146.95 191.5,146.95 191.5,0.4 190.45,-0.65 -0.15,-0.65
no net on TopLayer (solid, pour order 2): -0.15,146.25 191.15,146.25 191.5,145.9 191.5,0.05 -0.15,0.05

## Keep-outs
KeepOutLayer:
  the board outline again, w0.254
